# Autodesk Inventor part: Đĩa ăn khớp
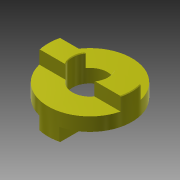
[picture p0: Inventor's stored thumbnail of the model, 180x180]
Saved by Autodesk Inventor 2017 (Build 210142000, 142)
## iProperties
Created: 2011-05
Part Number: Đĩa ăn khớp
Document SubType Name: Modeling
Designer: Administrator
Density: 7.85 g/cm^3
Material: Steel
Mass: 18294.2 g
Surface Area: 1704.24 cm^2
Volume: 2330.47 cm^3
Appearance: Yellow
Author: Administrator
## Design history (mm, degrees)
sketch "Sketch1"
  geometry: C1 r 125 at (0, 0); C2 r 52.5 at (0, 0)
  constraints: 2 centre point, 1 coincident
  dimensions: "d1" = 250 diameter of C1; "d4" = 105 diameter of C2
extrude "Extrusion2" new body sketch "Sketch1" distance "d5" = 120; taper "d6" = 0 deg
sketch "Sketch2"
  geometry: L1 (-121.347, -30)-(-43.084, -30); L2 (43.084, -30)-(121.347, -30); L3 (-121.347, 30)-(-43.084, 30); L4 (43.084, 30)-(121.347, 30); A1 r 52.5 centre (0, 0) between (-43.084, -30) and (43.084, -30) reference; A2 r 125 centre (0, 0) between (-121.347, 30) and (-121.347, -30) reference
  constraints: 8 end point, 8 point on circle, 4 parallel, 2 collinear, 2 horizontal
  dimensions: "d10" = 60 distance between parallel lines of L1 L3; "d11" = 30 distance from line of A1.centre L3
extrude "Extrusion3" cut sketch "Sketch2" distance "d12" = 40; taper "d13" = 0 deg
sketch "Sketch3"
  geometry: L1 (30, 121.347)-(30, 43.084); L2 (30, -43.084)-(30, -121.347); L3 (-30, 121.347)-(-30, 43.084); L4 (-30, -43.084)-(-30, -121.347); A1 r 52.5 centre (0, 0) between (30, 43.084) and (30, -43.084) reference; A2 r 125 centre (0, 0) between (-30, 121.347) and (30, 121.347) reference
  constraints: 8 end point, 8 point on circle, 4 parallel, 2 collinear, 2 vertical
  dimensions: "d16" = 30 distance from line of A1.centre L1; "d17" = 60 distance between parallel lines of L3 L1
extrude "Extrusion4" cut sketch "Sketch3" distance "d18" = 40; taper "d19" = 0 deg
chamfer "Chamfer1" distance "d20" = 2; stored, may be unused: second distance "d21" = 2, angle "d22" = 45 deg
body "Solid2"
other parameters: "d8" = 35, "d14" = 35
